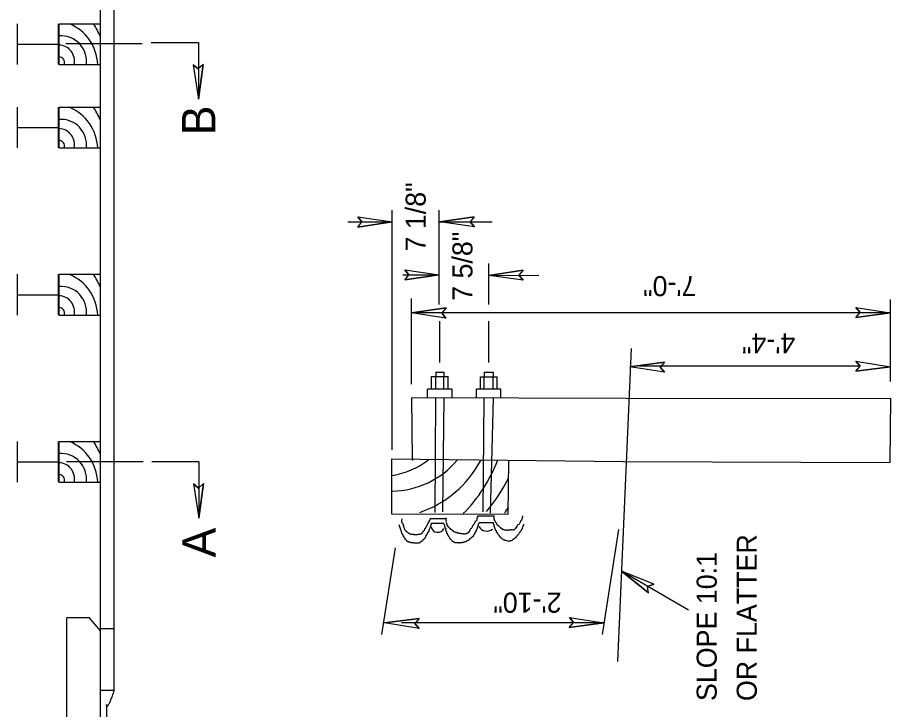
# Model space of a CAD drawing. Extents: x 12.2 to 54.5, y -7.8 to 16.1.
# Drawn here: x 50.1 to 52.714, y -5.573 to -3.502 of the extents above; entities that cross this region are included whole.
import ezdxf

# ---------------------------------------------------------------- set-up
doc = ezdxf.new("R2010")
doc.units = 0
for name, color, linetype in [('DETL-DIMS', 7, 'Continuous'), ('DETL-LINE', 7, 'Continuous'), ('DETL-NOTE', 7, 'Continuous'), ('DETL-PATT', 7, 'Continuous'), ('DETL-TITL', 7, 'Continuous')]:
    doc.layers.add(name, color=color, linetype=linetype)

msp = doc.modelspace()

# ---------------------------------------------------------------- linework, layer by layer
at = {"layer": 'DETL-DIMS'}
for p, q in [((50.2451, -3.5803), (50.474, -3.5803)), ((50.5011, -3.5774), (50.6427, -3.5774)), ((50.6427, -3.5777), (50.6427, -3.747)), ((50.1004, -3.582), (50.1004, -3.582)), ((50.1004, -3.582), (50.1004, -3.582)), ((50.626, -3.6439), (50.6427, -3.747)), ((50.626, -3.6439), (50.6413, -3.6565)), ((50.6562, -3.6434), (50.6413, -3.6565)), ((50.6562, -3.6434), (50.6427, -3.747)), ((50.1004, -3.832), (50.1004, -3.832)), ((50.1004, -3.832), (50.1004, -3.832)), ((51.1188, -4.0992), (51.222, -4.1144)), ((51.1188, -4.0992), (51.1317, -4.1144)), ((51.222, -4.7963), (51.222, -4.0794)), ((51.3628, -4.3612), (51.3628, -4.0794)), ((51.4679, -4.0987), (51.3647, -4.1144)), ((51.4679, -4.0987), (51.4551, -4.1139)), ((51.0893, -4.1143), (51.222, -4.1144)), ((51.1188, -4.1294), (51.222, -4.1144)), ((51.1188, -4.1294), (51.1317, -4.1144)), ((51.4681, -4.1289), (51.3647, -4.1144)), ((51.3647, -4.1144), (51.5219, -4.1144)), ((51.4681, -4.1289), (51.4551, -4.1139)), ((51.2595, -4.2573), (51.3628, -4.2725)), ((51.2595, -4.2573), (51.2724, -4.2724)), ((51.5111, -4.3612), (51.5111, -4.2391)), ((51.6143, -4.2583), (51.5111, -4.2741)), ((51.6143, -4.2583), (51.6014, -4.2735)), ((51.254, -4.2724), (51.3628, -4.2725)), ((51.2595, -4.2875), (51.2724, -4.2724)), ((51.2595, -4.2875), (51.3628, -4.2725)), ((51.5111, -4.2741), (51.6607, -4.2731)), ((51.6145, -4.2885), (51.5111, -4.2741)), ((51.6145, -4.2885), (51.6014, -4.2735)), ((50.1004, -4.332), (50.1004, -4.332)), ((50.1004, -4.332), (50.1004, -4.332)), ((51.28, -4.6001), (51.28, -4.3435)), ((52.714, -4.592), (52.714, -4.3462)), ((51.3834, -4.3717), (51.28, -4.3862)), ((51.3832, -4.4019), (51.28, -4.3862)), ((52.713, -4.3862), (51.28, -4.3862)), ((51.3834, -4.3717), (51.3703, -4.3867)), ((51.3832, -4.4019), (51.3703, -4.3867)), ((52.6096, -4.4007), (52.6226, -4.3857)), ((52.6096, -4.4007), (52.713, -4.3862)), ((52.6098, -4.3706), (52.713, -4.3862)), ((52.6098, -4.3706), (52.6226, -4.3857)), ((51.3647, -4.5353), (51.3647, -4.4112)), ((51.5111, -4.5353), (51.5111, -4.4112)), ((52.0373, -4.5336), (51.9339, -4.5474)), ((52.037, -4.5637), (51.9339, -4.5474)), ((52.6232, -4.5463), (51.9622, -4.5456)), ((52.0373, -4.5336), (52.0242, -4.5485)), ((52.6102, -4.5613), (52.6232, -4.5463)), ((52.6102, -4.5613), (52.7137, -4.5474)), ((52.6105, -4.5311), (52.7137, -4.5474)), ((52.6105, -4.5311), (52.6232, -4.5463)), ((52.037, -4.5637), (52.0242, -4.5485)), ((50.1004, -4.832), (50.1004, -4.832)), ((50.1004, -4.832), (50.1004, -4.832)), ((50.2474, -4.8313), (50.4763, -4.8313)), ((50.5022, -4.8314), (50.6438, -4.8314)), ((50.6438, -4.8317), (50.6438, -5.001)), ((50.6271, -4.8979), (50.6438, -5.001)), ((50.6271, -4.8979), (50.6424, -4.9105)), ((50.6573, -4.8974), (50.6424, -4.9105)), ((50.6573, -4.8974), (50.6438, -5.001)), ((51.9, -5.0347), (51.8503, -5.349)), ((51.2306, -5.09), (51.1901, -5.349)), ((51.9899, -5.2243), (51.9083, -5.1592)), ((52.0051, -5.1983), (51.9083, -5.1592)), ((52.1089, -5.2762), (51.9083, -5.1592)), ((52.0051, -5.1983), (51.9864, -5.2048)), ((51.9899, -5.2243), (51.9864, -5.2048)), ((51.3028, -5.3006), (51.1994, -5.3144)), ((51.3028, -5.3006), (51.2897, -5.3155)), ((51.7526, -5.2981), (51.8558, -5.3144)), ((51.7526, -5.2981), (51.7653, -5.3133)), ((51.3025, -5.3307), (51.1994, -5.3144)), ((51.8558, -5.3144), (51.2501, -5.3144)), ((51.3025, -5.3307), (51.2897, -5.3155)), ((51.7523, -5.3283), (51.7653, -5.3133)), ((51.7523, -5.3283), (51.8558, -5.3144))]:
    msp.add_line(p, q, dxfattribs=at)
for points in [[(50.626, -3.6439), (50.6427, -3.747), (50.6562, -3.6434), (50.6413, -3.6565)], [(51.1188, -4.0992), (51.222, -4.1144), (51.1188, -4.1294), (51.1317, -4.1144)], [(51.4681, -4.1289), (51.3647, -4.1144), (51.4679, -4.0987), (51.4551, -4.1139)], [(51.2595, -4.2573), (51.3628, -4.2725), (51.2595, -4.2875), (51.2724, -4.2724)], [(51.6145, -4.2885), (51.5111, -4.2741), (51.6143, -4.2583), (51.6014, -4.2735)], [(51.3832, -4.4019), (51.28, -4.3862), (51.3834, -4.3717), (51.3703, -4.3867)], [(52.6098, -4.3706), (52.713, -4.3862), (52.6096, -4.4007), (52.6226, -4.3857)], [(52.037, -4.5637), (51.9339, -4.5474), (52.0373, -4.5336), (52.0242, -4.5485)], [(52.6105, -4.5311), (52.7137, -4.5474), (52.6102, -4.5613), (52.6232, -4.5463)], [(50.6271, -4.8979), (50.6438, -5.001), (50.6573, -4.8974), (50.6424, -4.9105)], [(52.0051, -5.1983), (51.9083, -5.1592), (51.9899, -5.2243), (51.9864, -5.2048)], [(51.3025, -5.3307), (51.1994, -5.3144), (51.3028, -5.3006), (51.2897, -5.3155)], [(51.7526, -5.2981), (51.8558, -5.3144), (51.7523, -5.3283), (51.7653, -5.3133)]]:
    msp.add_lwpolyline(points, close=True, dxfattribs=at)
at = {"layer": 'DETL-LINE'}
for p, q in [((50.3897, -5.332), (50.3897, 2.7851)), ((50.3485, -5.332), (50.3485, 2.7601)), ((50.1004, -3.6429), (50.1004, -3.521)), ((50.223, -3.6429), (50.223, -3.521)), ((50.225, -3.6429), (50.225, -3.521)), ((50.225, -3.521), (50.3485, -3.521)), ((50.3485, -3.6429), (50.3485, -3.521)), ((50.1004, -3.582), (50.223, -3.582)), ((50.3485, -3.582), (50.3485, -3.582)), ((50.225, -3.6429), (50.3485, -3.6429)), ((50.1004, -3.8929), (50.1004, -3.771)), ((50.223, -3.8929), (50.223, -3.771)), ((50.225, -3.8929), (50.225, -3.771)), ((50.225, -3.771), (50.3485, -3.771)), ((50.3485, -3.8929), (50.3485, -3.771)), ((50.1004, -3.832), (50.223, -3.832)), ((50.3485, -3.832), (50.3485, -3.832)), ((50.225, -3.8929), (50.3485, -3.8929)), ((50.1004, -4.3929), (50.1004, -4.271)), ((50.223, -4.3929), (50.223, -4.271)), ((50.225, -4.3929), (50.225, -4.271)), ((50.225, -4.271), (50.3485, -4.271)), ((50.3485, -4.3929), (50.3485, -4.271)), ((50.1004, -4.332), (50.223, -4.332)), ((50.3485, -4.332), (50.3485, -4.332)), ((50.3485, -4.332), (50.3485, -4.332)), ((50.225, -4.3929), (50.3485, -4.3929)), ((51.9379, -4.4933), (51.8963, -5.4292)), ((51.353, -4.5636), (51.3764, -4.5636)), ((51.353, -4.5636), (51.353, -4.577)), ((51.3764, -4.5636), (51.3764, -4.577)), ((51.4978, -4.5641), (51.5244, -4.5641)), ((51.4978, -4.5641), (51.4978, -4.5775)), ((51.5244, -4.5641), (51.5244, -4.5775)), ((51.3398, -4.577), (51.3896, -4.577)), ((51.3398, -4.6144), (51.3398, -4.577)), ((51.353, -4.6144), (51.353, -4.577)), ((51.3764, -4.6144), (51.3764, -4.577)), ((51.3896, -4.6144), (51.3896, -4.577)), ((51.4862, -4.6149), (51.4862, -4.5775)), ((51.4862, -4.5775), (51.536, -4.5775)), ((51.4978, -4.6149), (51.4978, -4.5775)), ((51.5244, -4.6149), (51.5244, -4.5775)), ((51.536, -4.6149), (51.536, -4.5775)), ((51.4013, -4.6144), (51.3281, -4.6144)), ((51.3281, -4.6404), (51.3281, -4.6144)), ((51.4013, -4.6404), (51.4013, -4.6144)), ((51.4745, -4.6409), (51.4745, -4.6149)), ((51.5477, -4.6149), (51.4745, -4.6149)), ((51.5477, -4.6409), (51.5477, -4.6149)), ((51.924, -4.6425), (51.28, -4.6404)), ((51.28, -4.6404), (51.2816, -4.8264)), ((51.3506, -4.9835), (51.353, -4.6408)), ((51.3764, -4.6409), (51.3724, -4.9814)), ((51.494, -4.982), (51.4978, -4.6413)), ((51.5244, -4.6414), (51.5158, -4.9853)), ((51.924, -4.6425), (52.714, -4.642)), ((52.714, -4.642), (52.7122, -4.834)), ((50.1004, -4.8929), (50.1004, -4.771)), ((50.223, -4.8929), (50.223, -4.771)), ((50.225, -4.8929), (50.225, -4.771)), ((50.225, -4.771), (50.3485, -4.771)), ((50.3485, -4.8929), (50.3485, -4.771)), ((50.1004, -4.832), (50.223, -4.832)), ((50.3485, -4.832), (50.3485, -4.832)), ((51.2203, -4.8232), (51.2197, -4.9876)), ((51.2203, -4.8232), (51.9136, -4.8316)), ((51.5697, -4.9889), (51.5713, -4.8287)), ((51.9136, -4.8316), (52.7122, -4.834)), ((50.225, -4.8929), (50.3485, -4.8929)), ((51.2197, -4.9876), (51.5697, -4.9889)), ((51.3364, -5.0022), (51.3837, -5.0022)), ((51.3403, -5.016), (51.3772, -5.016)), ((51.4798, -4.9936), (51.5281, -4.9936)), ((51.4822, -5.0141), (51.5253, -5.0141)), ((50.248, -5.7641), (50.2481, -5.2986)), ((50.3149, -5.2986), (50.2481, -5.2986)), ((50.3485, -5.3384), (50.3151, -5.2985)), ((50.3485, -5.7641), (50.3485, -5.332)), ((50.3897, -5.332), (50.3485, -5.332)), ((50.3897, -5.5161), (50.3897, -5.332)), ((50.3897, -5.5161), (50.3485, -5.5161))]:
    msp.add_line(p, q, dxfattribs=at)
for centre, radius, start, end in [((51.3584, -5.0233), 0.02, 188.3494, 336.752), ((51.5054, -5.0127), 0.0269, 209.5517, 308.2673)]:
    msp.add_arc(centre, radius, start, end, dxfattribs=at)
for points in [[(51.2422, -5.0196), (51.2442, -5.0253), (51.2447, -5.0281), (51.2456, -5.0305), (51.2466, -5.0343), (51.2475, -5.0348), (51.2476, -5.0366), (51.2481, -5.0381), (51.2485, -5.0401), (51.249, -5.0401), (51.249, -5.0419), (51.2504, -5.0439), (51.2504, -5.0453), (51.2514, -5.0467), (51.2519, -5.0466), (51.2529, -5.0505), (51.2539, -5.0514), (51.2539, -5.0519), (51.2543, -5.0534), (51.2552, -5.0534), (51.2557, -5.0548), (51.2562, -5.0567), (51.2572, -5.0567), (51.2572, -5.0581), (51.2582, -5.0596), (51.2587, -5.0601), (51.2592, -5.0609), (51.26, -5.0609), (51.26, -5.0624), (51.2615, -5.0643), (51.263, -5.0652), (51.2639, -5.0657), (51.2644, -5.0676), (51.2658, -5.0686), (51.2658, -5.0691), (51.2673, -5.07), (51.2692, -5.0704), (51.2706, -5.0709), (51.2725, -5.0714), (51.273, -5.0718), (51.2744, -5.0723), (51.2773, -5.0723), (51.2783, -5.0733), (51.2801, -5.0733), (51.284, -5.0742), (51.2873, -5.0742), (51.2883, -5.0747), (51.2888, -5.0747), (51.2901, -5.075), (51.2916, -5.0747), (51.293, -5.075), (51.2949, -5.075), (51.2978, -5.075), (51.2997, -5.0746), (51.3025, -5.075), (51.3039, -5.0731), (51.3054, -5.0731), (51.3068, -5.0716), (51.3083, -5.0711), (51.3086, -5.0701), (51.3106, -5.0698), (51.3116, -5.0683), (51.3121, -5.0688), (51.3134, -5.0673), (51.3134, -5.0668), (51.3148, -5.0658), (51.3148, -5.0653), (51.3163, -5.0644), (51.3158, -5.064), (51.3177, -5.063), (51.3201, -5.0605), (51.32, -5.0592), (51.3215, -5.0592), (51.3225, -5.0567), (51.3238, -5.0519), (51.3253, -5.0514), (51.3262, -5.0491), (51.3272, -5.0486), (51.3277, -5.0457), (51.329, -5.0438), (51.33, -5.0419), (51.3314, -5.0413), (51.3332, -5.0347), (51.3342, -5.0332), (51.3347, -5.0328), (51.3351, -5.0318), (51.3361, -5.0285), (51.3375, -5.0252), (51.3375, -5.0232), (51.3384, -5.0212), (51.3394, -5.0184), (51.3403, -5.016), (51.3408, -5.0156)], [(51.2512, -5.0032), (51.2507, -5.0057), (51.2502, -5.007), (51.2502, -5.0113), (51.2507, -5.0128), (51.2512, -5.0147), (51.2522, -5.0157), (51.2522, -5.0161), (51.2537, -5.0175), (51.2546, -5.019), (51.255, -5.02), (51.2551, -5.0205), (51.256, -5.0232), (51.2565, -5.0232), (51.256, -5.0247), (51.257, -5.0275), (51.2575, -5.029), (51.2575, -5.0305), (51.258, -5.0308), (51.259, -5.0338), (51.2594, -5.0343), (51.2604, -5.0356), (51.2618, -5.0371), (51.2623, -5.0385), (51.2638, -5.0395), (51.2647, -5.04), (51.2651, -5.0408), (51.2656, -5.0413), (51.2666, -5.0418), (51.2676, -5.0428), (51.269, -5.0433), (51.2699, -5.0442), (51.2714, -5.0452), (51.2714, -5.0456), (51.2738, -5.0465), (51.2738, -5.047), (51.2762, -5.048), (51.2776, -5.0484), (51.279, -5.0484), (51.2805, -5.0489), (51.2852, -5.0489), (51.2862, -5.0499), (51.2867, -5.0499), (51.2886, -5.0493), (51.2914, -5.0498), (51.2943, -5.0493), (51.2976, -5.0493), (51.3, -5.0488), (51.3034, -5.0488), (51.3042, -5.0483), (51.3047, -5.0488), (51.3072, -5.0477), (51.3085, -5.0473), (51.309, -5.0468), (51.3105, -5.0458), (51.3119, -5.0454), (51.3129, -5.0439), (51.3134, -5.0424), (51.3147, -5.0415), (51.3152, -5.0406), (51.3161, -5.0396), (51.3166, -5.0381), (51.3176, -5.0372), (51.3184, -5.0367), (51.3184, -5.0353), (51.3194, -5.0353), (51.3194, -5.0339), (51.3204, -5.0324), (51.3209, -5.0328), (51.3213, -5.0309), (51.3223, -5.0309), (51.3223, -5.0295), (51.3232, -5.0281), (51.3237, -5.0271), (51.3241, -5.0266), (51.3251, -5.0252), (51.3261, -5.0238), (51.3266, -5.0228), (51.3266, -5.0223), (51.327, -5.0209), (51.328, -5.0209), (51.3275, -5.0195), (51.3289, -5.018), (51.3293, -5.018), (51.3303, -5.0151), (51.3308, -5.0151), (51.3317, -5.0137), (51.3322, -5.0132), (51.3317, -5.0122), (51.3327, -5.0109), (51.3331, -5.0094), (51.3336, -5.0084), (51.3336, -5.0079), (51.3345, -5.0065), (51.335, -5.0065), (51.3355, -5.0051), (51.3355, -5.0036)], [(51.3355, -5.0036), (51.3364, -5.0027), (51.3364, -5.0022)], [(51.377, -5.0177), (51.3765, -5.0177), (51.3774, -5.0201), (51.3784, -5.021), (51.3789, -5.0244), (51.3794, -5.0262), (51.3799, -5.0282), (51.3809, -5.031), (51.3819, -5.031), (51.3819, -5.0344), (51.3823, -5.0362), (51.3833, -5.0362), (51.3828, -5.0377), (51.3837, -5.0406), (51.3847, -5.041), (51.3848, -5.0439), (51.3857, -5.0454), (51.3867, -5.0458), (51.3871, -5.0482), (51.3876, -5.0497), (51.3886, -5.0501), (51.3891, -5.051), (51.3891, -5.0525), (51.3906, -5.0539), (51.3906, -5.0553), (51.3915, -5.0567), (51.3934, -5.0597), (51.3944, -5.0615), (51.3953, -5.062), (51.3958, -5.0629), (51.3967, -5.0634), (51.3982, -5.0653), (51.4011, -5.0682), (51.403, -5.0696), (51.4044, -5.0705), (51.4064, -5.0705), (51.4077, -5.0719), (51.4135, -5.0734), (51.4159, -5.0734), (51.4173, -5.0738), (51.4202, -5.0738), (51.4215, -5.0743), (51.4235, -5.0742), (51.4249, -5.0738), (51.4297, -5.0737), (51.4311, -5.0732), (51.4325, -5.0732), (51.4354, -5.0722), (51.4368, -5.0722), (51.4373, -5.0717), (51.4382, -5.0717), (51.4425, -5.0702), (51.444, -5.0702), (51.4454, -5.0693), (51.4458, -5.0689), (51.4497, -5.0669), (51.451, -5.0659), (51.451, -5.0654), (51.4525, -5.0654), (51.4544, -5.0635), (51.4558, -5.062), (51.4572, -5.0611), (51.4572, -5.0602), (51.4587, -5.0597), (51.4596, -5.0582), (51.4605, -5.0582), (51.462, -5.0562), (51.4644, -5.0558), (51.4657, -5.0524), (51.4671, -5.0501), (51.4686, -5.0501), (51.4686, -5.0486), (51.4691, -5.0471), (51.4701, -5.0471), (51.47, -5.0457), (51.4704, -5.0443), (51.4714, -5.0428), (51.4724, -5.0409), (51.4729, -5.0414), (51.4743, -5.039), (51.4743, -5.0371), (51.4748, -5.0356), (51.4756, -5.0333), (51.4766, -5.0318), (51.4771, -5.0308), (51.478, -5.0285), (51.4785, -5.027), (51.479, -5.0247), (51.4803, -5.0199), (51.4813, -5.0179), (51.4822, -5.0156), (51.4822, -5.0141)], [(51.3835, -5.0005), (51.3831, -5.0005), (51.3831, -5.0053), (51.3836, -5.0066), (51.3836, -5.0119), (51.3846, -5.0123), (51.3841, -5.0138), (51.3846, -5.0153), (51.3851, -5.0166), (51.3856, -5.0191), (51.3861, -5.02), (51.3861, -5.0205), (51.3866, -5.0219), (51.3879, -5.0219), (51.3875, -5.0234), (51.3884, -5.0248), (51.3894, -5.0253), (51.3889, -5.0262), (51.3909, -5.0276), (51.3922, -5.0291), (51.3937, -5.0295), (51.3947, -5.0305), (51.3957, -5.0309), (51.3957, -5.0319), (51.397, -5.0333), (51.3985, -5.0343), (51.4, -5.0348), (51.4009, -5.0366), (51.4014, -5.0366), (51.4028, -5.0381), (51.4042, -5.039), (51.4057, -5.0395), (51.4062, -5.0409), (51.4071, -5.0409), (51.409, -5.0413), (51.4105, -5.0423), (51.4128, -5.0428), (51.4143, -5.0433), (51.4158, -5.0432), (51.4158, -5.0442), (51.4171, -5.0447), (51.419, -5.0447), (51.4205, -5.0442), (51.4219, -5.0451), (51.4223, -5.0455), (51.4233, -5.0455), (51.4248, -5.046), (51.4261, -5.046), (51.4276, -5.0464), (51.4286, -5.0469), (51.4324, -5.0469), (51.4343, -5.0474), (51.4409, -5.0473), (51.4438, -5.0464), (51.4457, -5.0458), (51.4466, -5.045), (51.4476, -5.045), (51.4505, -5.044), (51.4509, -5.043), (51.4529, -5.041), (51.4543, -5.0406), (51.4543, -5.0397), (51.4548, -5.0382), (51.4595, -5.031), (51.4608, -5.0309), (51.4604, -5.0296), (51.4623, -5.0266), (51.4622, -5.0253), (51.4637, -5.0238), (51.4642, -5.0223), (51.4652, -5.021), (51.468, -5.0181), (51.4689, -5.0166), (51.4699, -5.0147), (51.4707, -5.0118), (51.4736, -5.0085), (51.4764, -5.0061), (51.4764, -5.0017), (51.4769, -5.0004), (51.4769, -4.9989), (51.4778, -4.9989), (51.4783, -4.996), (51.4798, -4.9936)], [(51.524, -5.0147), (51.525, -5.0181), (51.526, -5.0195), (51.526, -5.0228), (51.5265, -5.0247), (51.5275, -5.0266), (51.5284, -5.0281), (51.5284, -5.0295), (51.5289, -5.0295), (51.5294, -5.0319), (51.5298, -5.0333), (51.5303, -5.0338), (51.5318, -5.0366), (51.5323, -5.0371), (51.5333, -5.039), (51.5333, -5.0405), (51.5338, -5.0419), (51.5346, -5.0418), (51.5352, -5.0438), (51.5361, -5.0443), (51.5371, -5.0466), (51.5381, -5.0476), (51.5386, -5.0486), (51.539, -5.05), (51.5394, -5.0495), (51.5409, -5.0513), (51.5419, -5.0528), (51.5424, -5.0538), (51.5433, -5.0543), (51.5437, -5.0552), (51.5452, -5.0556), (51.5452, -5.0571), (51.5467, -5.0585), (51.5486, -5.06), (51.55, -5.0613), (51.5515, -5.0623), (51.5525, -5.0628), (51.5529, -5.0633), (51.5543, -5.0633), (51.5548, -5.0642), (51.5557, -5.0647), (51.5572, -5.0656), (51.5591, -5.0661), (51.5605, -5.0665), (51.561, -5.067), (51.562, -5.067), (51.5677, -5.0689), (51.5733, -5.0689), (51.5768, -5.0684), (51.5781, -5.0674), (51.5795, -5.0674), (51.5829, -5.0659), (51.5843, -5.064), (51.5858, -5.063), (51.5872, -5.0625), (51.591, -5.0587), (51.5933, -5.0582), (51.5947, -5.0549), (51.5976, -5.0524), (51.5985, -5.051), (51.599, -5.0505), (51.6, -5.0491), (51.6014, -5.0476), (51.6042, -5.0433), (51.6052, -5.0428), (51.6056, -5.0414), (51.6066, -5.0395), (51.6085, -5.0385), (51.6089, -5.0371), (51.6099, -5.0356), (51.6109, -5.0332), (51.6122, -5.0323), (51.6127, -5.0308), (51.6127, -5.0294), (51.6141, -5.0256), (51.6141, -5.0237), (51.6155, -5.0217), (51.6165, -5.0194), (51.617, -5.0189)], [(51.5263, -4.994), (51.5268, -4.995), (51.5263, -4.9969), (51.5264, -5.0016), (51.5269, -5.0031), (51.5273, -5.0041), (51.5278, -5.0055), (51.5283, -5.0079), (51.5292, -5.0083), (51.5302, -5.0112), (51.5322, -5.0141), (51.5327, -5.0146), (51.5331, -5.0156), (51.5345, -5.0169), (51.535, -5.0188), (51.5355, -5.0198), (51.5369, -5.0208), (51.5379, -5.0221), (51.5407, -5.0236), (51.5417, -5.025), (51.5422, -5.0255), (51.5446, -5.0268), (51.5461, -5.0298), (51.5485, -5.0303), (51.5494, -5.0311), (51.5503, -5.0316), (51.5499, -5.0326), (51.5523, -5.034), (51.5536, -5.034), (51.5551, -5.0345), (51.5561, -5.0354), (51.5565, -5.0354), (51.558, -5.0358), (51.5599, -5.0363), (51.5666, -5.0362), (51.5666, -5.0367), (51.568, -5.0362), (51.5694, -5.0362), (51.5708, -5.0354), (51.5723, -5.0357), (51.5751, -5.0357), (51.577, -5.0353), (51.5784, -5.0348), (51.5875, -5.0348), (51.5884, -5.0338), (51.5889, -5.0338), (51.5908, -5.0313), (51.5923, -5.0304), (51.5927, -5.0294), (51.5936, -5.029), (51.5936, -5.028), (51.5951, -5.029), (51.5951, -5.0265), (51.5965, -5.0247), (51.5975, -5.0217), (51.6018, -5.0184), (51.6036, -5.0174), (51.605, -5.0141), (51.606, -5.0126), (51.6069, -5.0098), (51.6078, -5.0078), (51.6088, -5.0063), (51.6097, -5.0063), (51.6112, -5.0035), (51.6116, -5.0021), (51.6121, -5.0002), (51.6121, -4.9982), (51.6125, -4.9968), (51.613, -4.9949), (51.6135, -4.9935)]]:
    msp.add_spline(points, degree=3, dxfattribs=at)
msp.add_open_spline([(50.3897, -5.5161), (50.3679, -5.578), (50.3663, -5.5424), (50.3687, -5.6641)], degree=2, dxfattribs=at)
at = {"layer": 'DETL-PATT'}
for centre, radius, start, end in [((51.1781, -4.6233), 0.2538, 280.0268, 306.912), ((51.2168, -4.6584), 0.2617, 271.1987, 319.858), ((51.2129, -4.5973), 0.2391, 286.6952, 287.6506), ((51.2038, -4.6799), 0.3197, 288.3721, 332.445), ((51.1115, -4.6661), 0.4557, 315.2141, 339.1469), ((51.0856, -4.6313), 0.5456, 320.1581, 332.7687), ((50.643, -4.4129), 1.0804, 327.9748, 329.0858)]:
    msp.add_arc(centre, radius, start, end, dxfattribs=at)
for centre, major_axis, start_param, end_param in [((50.205, -3.6483), (0, 0.137), 4.750897, 5.899278), ((50.0724, -3.6872), (0, 0.3071), 5.144981, 5.283467), ((50.2309, -3.6344), (0, 0.0772), 4.600695, 6.361038), ((50.2243, -3.6323), (0, 0.0472), 4.485117, 6.270221), ((50.2243, -3.6379), (0, 0.0174), 4.485117, 6.270221), ((50.205, -3.8983), (0, 0.137), 4.750897, 5.899278), ((50.0724, -3.9372), (0, 0.3071), 5.144981, 5.283467), ((50.2309, -3.8844), (0, 0.0772), 4.600695, 6.361038), ((50.2243, -3.8823), (0, 0.0472), 4.485117, 6.270221), ((50.2243, -3.8879), (0, 0.0174), 4.485117, 6.270221), ((50.205, -4.3983), (0, 0.137), 4.750897, 5.899278), ((50.0724, -4.4372), (0, 0.3071), 5.144981, 5.283467), ((50.2309, -4.3844), (0, 0.0772), 4.600695, 6.361038), ((50.2243, -4.3823), (0, 0.0472), 4.485117, 6.270221), ((50.2243, -4.3879), (0, 0.0174), 4.485117, 6.270221), ((50.205, -4.8983), (0, 0.137), 4.750897, 5.899278), ((50.0724, -4.9372), (0, 0.3071), 5.144981, 5.283467), ((50.2309, -4.8844), (0, 0.0772), 4.600695, 6.361038), ((50.2243, -4.8823), (0, 0.0472), 4.485117, 6.270221), ((50.2243, -4.8879), (0, 0.0174), 4.485117, 6.270221)]:
    msp.add_ellipse(centre, major_axis=major_axis, ratio=0.989796, start_param=start_param, end_param=end_param, dxfattribs=at)

# ---------------------------------------------------------------- texts
at = {"layer": 'DETL-NOTE'}
for s, rotation, p in [('7 1/8"', 90, (51.3224, -4.2027)), ('7 5/8"', 90, (51.4625, -4.3504)), ('7\'-0"', 180, (52.1329, -4.2763)), ('4\'-4"', 180, (52.429, -4.4472)), ('OR FLATTER', 90, (52.3136, -5.548)), ('SLOPE 10:1', 90, (52.1936, -5.548)), ('2\'-10"', 180, (51.7291, -5.2236))]:
    msp.add_text(s, height=0.06, rotation=rotation, dxfattribs=at).set_placement(p)
at = {"layer": 'DETL-TITL'}
for s, p in [('B', (50.6927, -3.855)), ('A', (50.6938, -5.1184))]:
    msp.add_text(s, height=0.1, rotation=90, dxfattribs=at).set_placement(p)

doc.saveas('drawing.dxf')
